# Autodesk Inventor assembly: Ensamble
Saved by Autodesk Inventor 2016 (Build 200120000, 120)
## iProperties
Created: 2017-06
Part Number: Ensamble
Document SubType Name: Assembly
Designer: Administrator
Author: Administrator
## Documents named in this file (6)
- c:\worker\convert-fusion-jun-2017\tmp\job-1\12\output\files\680d4b69-c182-4e82-8b38-9dde0e804810\Ensamble.iam
- c:\worker\convert-fusion-jun-2017\tmp\job-1\12\output\files\680d4b69-c182-4e82-8b38-9dde0e804810\Cono 1.ipt
- c:\worker\convert-fusion-jun-2017\tmp\job-1\12\output\files\680d4b69-c182-4e82-8b38-9dde0e804810\Cono 2.ipt
- c:\worker\convert-fusion-jun-2017\tmp\job-1\12\output\files\680d4b69-c182-4e82-8b38-9dde0e804810\Hilo.ipt
- c:\worker\convert-fusion-jun-2017\tmp\job-1\12\output\files\680d4b69-c182-4e82-8b38-9dde0e804810\Base .ipt
- c:\worker\convert-fusion-jun-2017\tmp\job-1\12\output\files\680d4b69-c182-4e82-8b38-9dde0e804810\Bloqueo.ipt
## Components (5 placed, 5 different names)
1. Cono 1:1
2. Cono 2:1
3. Hilo:1
4. Base :1
5. Bloqueo:1
